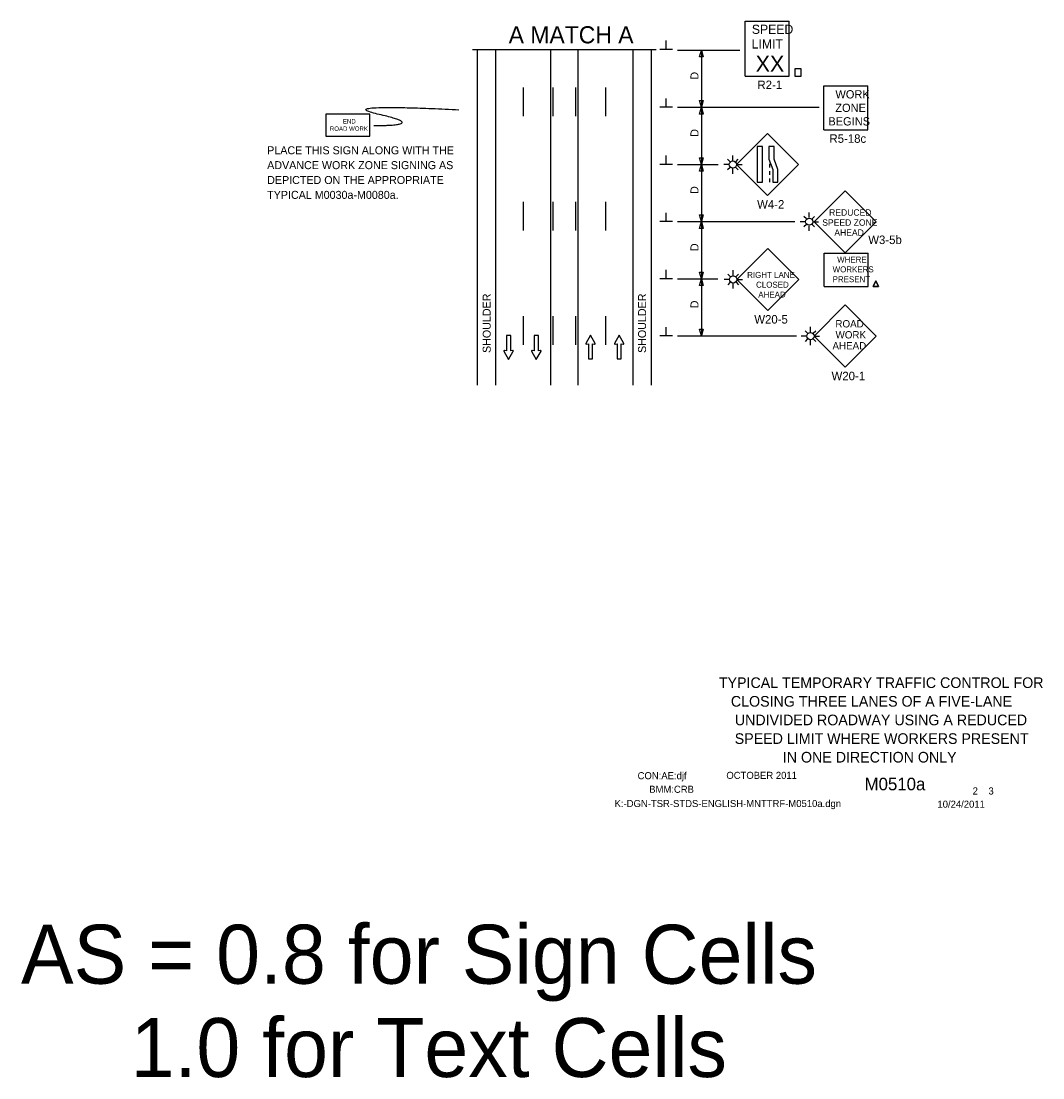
# Model space of a CAD drawing. Extents: x 16730 to 19504, y 5697 to 6911.
# Drawn here: x 17580 to 18474, y 5697 to 6621 of the extents above; entities that cross this region are included whole.
import ezdxf

# ---------------------------------------------------------------- set-up
doc = ezdxf.new("R2010")
doc.units = 0
for name, color, linetype in [('ALI_LEGAL_EX', 7, 'Continuous'), ('BORDER', 7, 'Continuous'), ('BORDER_SIGNAL_WO', 7, 'Continuous'), ('MT_SCRATCH_LEVEL_E', 7, 'Continuous'), ('PAVT_EDGE_EX', 7, 'Continuous'), ('TRAFFIC_SIGNS_PR', 7, 'Continuous'), ('TYPICAL_TEXT_DIMEN_PR', 7, 'Continuous')]:
    doc.layers.add(name, color=color, linetype=linetype)

msp = doc.modelspace()

# ---------------------------------------------------------------- linework, layer by layer
at = {"layer": 'ALI_LEGAL_EX'}
for points in [[(18019.48, 6563.08), (18019.48, 6538.08)], [(18045.48, 6563.08), (18045.48, 6538.08)], [(18065.48, 6563.08), (18065.48, 6538.08)], [(18091.48, 6563.08), (18091.48, 6538.08)], [(18019.48, 6463.08), (18019.48, 6438.08)], [(18045.48, 6463.08), (18045.48, 6438.08)], [(18065.48, 6463.08), (18065.48, 6438.08)], [(18091.48, 6463.08), (18091.48, 6438.08)], [(18019.48, 6363.08), (18019.48, 6338.08)], [(18045.48, 6363.08), (18045.48, 6338.08)], [(18065.48, 6363.08), (18065.48, 6338.08)], [(18091.48, 6363.08), (18091.48, 6338.08)]]:
    msp.add_lwpolyline(points, dxfattribs=at)
at = {"layer": 'MT_SCRATCH_LEVEL_E'}
for p, q in [((18008.68, 6346.05), (18004.93, 6346.05)), ((18004.93, 6346.05), (18004.93, 6332.79)), ((18008.68, 6346.05), (18004.93, 6346.05)), ((18004.93, 6346.05), (18004.93, 6332.79)), ((18008.68, 6332.79), (18008.68, 6346.05)), ((18008.68, 6332.79), (18008.68, 6346.05)), ((18032.93, 6346.05), (18029.19, 6346.05)), ((18029.19, 6346.05), (18029.19, 6332.79)), ((18032.93, 6346.05), (18029.19, 6346.05)), ((18029.19, 6346.05), (18029.19, 6332.79)), ((18032.93, 6332.79), (18032.93, 6346.05)), ((18032.93, 6332.79), (18032.93, 6346.05)), ((18078.44, 6346.51), (18074.33, 6339.27)), ((18078.44, 6346.51), (18074.33, 6339.27)), ((18082.59, 6339.27), (18078.44, 6346.51)), ((18082.59, 6339.27), (18078.44, 6346.51)), ((18103.53, 6346.51), (18099.42, 6339.27)), ((18103.53, 6346.51), (18099.42, 6339.27)), ((18107.68, 6339.27), (18103.53, 6346.51)), ((18107.68, 6339.27), (18103.53, 6346.51)), ((18002.68, 6332.42), (18006.82, 6325.18)), ((18002.68, 6332.42), (18006.82, 6325.18)), ((18004.93, 6332.79), (18003.16, 6333.11)), ((18004.93, 6332.79), (18003.16, 6333.11)), ((18006.82, 6325.18), (18010.94, 6332.42)), ((18006.82, 6325.18), (18010.94, 6332.42)), ((18010.45, 6333.11), (18008.68, 6332.79)), ((18010.45, 6333.11), (18008.68, 6332.79)), ((18026.93, 6332.42), (18031.08, 6325.18)), ((18026.93, 6332.42), (18031.08, 6325.18)), ((18029.19, 6332.79), (18027.41, 6333.11)), ((18029.19, 6332.79), (18027.41, 6333.11)), ((18031.08, 6325.18), (18035.19, 6332.42)), ((18031.08, 6325.18), (18035.19, 6332.42)), ((18034.71, 6333.11), (18032.93, 6332.79)), ((18034.71, 6333.11), (18032.93, 6332.79)), ((18074.81, 6338.59), (18076.59, 6338.9)), ((18074.81, 6338.59), (18076.59, 6338.9)), ((18076.59, 6338.9), (18076.59, 6325.64)), ((18076.59, 6338.9), (18076.59, 6325.64)), ((18080.33, 6325.64), (18080.33, 6338.9)), ((18080.33, 6338.9), (18082.11, 6338.59)), ((18080.33, 6325.64), (18080.33, 6338.9)), ((18080.33, 6338.9), (18082.11, 6338.59)), ((18099.9, 6338.59), (18101.68, 6338.9)), ((18099.9, 6338.59), (18101.68, 6338.9)), ((18101.68, 6338.9), (18101.68, 6325.64)), ((18101.68, 6338.9), (18101.68, 6325.64)), ((18105.42, 6325.64), (18105.42, 6338.9)), ((18105.42, 6338.9), (18107.2, 6338.59)), ((18105.42, 6325.64), (18105.42, 6338.9)), ((18105.42, 6338.9), (18107.2, 6338.59)), ((18076.59, 6325.64), (18080.33, 6325.64)), ((18076.59, 6325.64), (18080.33, 6325.64)), ((18101.68, 6325.64), (18105.42, 6325.64)), ((18101.68, 6325.64), (18105.42, 6325.64))]:
    msp.add_line(p, q, dxfattribs=at)
for centre, start, end in [((18003.09, 6332.65), 80.03619, 209.77312), ((18003.09, 6332.65), 80.03619, 209.77312), ((18010.53, 6332.65), 330.42484, 99.96381), ((18010.53, 6332.65), 330.42484, 99.96381), ((18027.34, 6332.65), 80.03619, 209.77312), ((18027.34, 6332.65), 80.03619, 209.77312), ((18034.78, 6332.65), 330.42484, 99.96381), ((18034.78, 6332.65), 330.42484, 99.96381), ((18074.74, 6339.05), 150.42484, 279.96381), ((18074.74, 6339.05), 150.42484, 279.96381), ((18082.18, 6339.05), 260.03619, 29.77312), ((18082.18, 6339.05), 260.03619, 29.77312), ((18099.83, 6339.05), 150.42484, 279.96381), ((18099.83, 6339.05), 150.42484, 279.96381), ((18107.27, 6339.05), 260.03619, 29.77312), ((18107.27, 6339.05), 260.03619, 29.77312)]:
    msp.add_arc(centre, 0.463, start, end, dxfattribs=at)
at = {"layer": 'PAVT_EDGE_EX'}
for p, q in [((17979.48, 6596.43), (17979.48, 6302.77)), ((17995.48, 6596.43), (17995.48, 6302.77)), ((18043.48, 6596.43), (18043.48, 6302.77)), ((18067.48, 6596.43), (18067.48, 6302.77)), ((18115.48, 6596.43), (18115.48, 6302.77)), ((18131.48, 6596.43), (18131.48, 6302.77))]:
    msp.add_line(p, q, dxfattribs=at)
at = {"layer": 'TRAFFIC_SIGNS_PR'}
for p, q in [((18213.83, 6621.17), (18252.23, 6621.17)), ((18213.83, 6573.17), (18213.83, 6621.17)), ((18252.23, 6573.17), (18252.23, 6621.17)), ((18213.83, 6573.17), (18252.23, 6573.17)), ((18282.71, 6526.17), (18282.71, 6564.57)), ((18282.71, 6564.57), (18321.11, 6564.57)), ((18321.11, 6526.17), (18321.11, 6564.57)), ((18282.71, 6526.17), (18321.11, 6526.17)), ((18233.28, 6522.93), (18206.12, 6495.78)), ((18260.43, 6495.78), (18233.28, 6522.93)), ((18200.52, 6498.23), (18198.42, 6500.34)), ((18203.04, 6499.28), (18203.04, 6503.78)), ((18205.55, 6498.23), (18207.66, 6500.34)), ((18199.88, 6495.72), (18195.05, 6495.72)), ((18200.52, 6493.21), (18198.42, 6491.1)), ((18203.04, 6487.75), (18203.04, 6492.17)), ((18205.55, 6493.21), (18207.66, 6491.1)), ((18206.12, 6495.78), (18233.28, 6468.63)), ((18206.19, 6495.72), (18211.07, 6495.72)), ((18233.28, 6468.63), (18260.43, 6495.78)), ((18234.92, 6496.27), (18234.92, 6493.07)), ((18234.92, 6489.87), (18234.92, 6486.67)), ((18234.92, 6483.47), (18234.92, 6480.27)), ((18301.14, 6472.83), (18273.99, 6445.68)), ((18328.3, 6445.68), (18301.14, 6472.83)), ((18269.79, 6449.31), (18269.79, 6453.81)), ((18266.64, 6445.76), (18261.8, 6445.76)), ((18267.28, 6448.27), (18265.17, 6450.38)), ((18267.28, 6443.24), (18265.17, 6441.13)), ((18272.3, 6448.27), (18274.41, 6450.38)), ((18272.3, 6443.24), (18274.41, 6441.14)), ((18272.94, 6445.76), (18277.82, 6445.76)), ((18273.99, 6445.68), (18301.14, 6418.53)), ((18301.14, 6418.53), (18328.3, 6445.68)), ((18269.79, 6437.79), (18269.79, 6442.2)), ((18233.57, 6422.38), (18206.42, 6395.23)), ((18260.72, 6395.23), (18233.57, 6422.38)), ((18282.88, 6418.35), (18321.28, 6418.35)), ((18282.88, 6389.03), (18282.88, 6418.35)), ((18321.28, 6389.03), (18321.28, 6418.35)), ((18200.75, 6397.74), (18198.64, 6399.85)), ((18203.26, 6398.78), (18203.26, 6403.28)), ((18205.78, 6397.74), (18207.89, 6399.85)), ((18200.11, 6395.23), (18195.27, 6395.23)), ((18200.75, 6392.71), (18198.64, 6390.6)), ((18203.26, 6387.26), (18203.26, 6391.67)), ((18205.78, 6392.71), (18207.88, 6390.61)), ((18206.42, 6395.23), (18211.3, 6395.23)), ((18206.42, 6395.23), (18233.57, 6368.07)), ((18233.57, 6368.07), (18260.72, 6395.23)), ((18282.88, 6389.03), (18321.28, 6389.03)), ((18301.17, 6372.88), (18273.99, 6345.69)), ((18328.36, 6345.69), (18301.17, 6372.88)), ((18268.32, 6348.2), (18266.21, 6350.31)), ((18270.83, 6349.25), (18270.83, 6353.75)), ((18273.35, 6348.2), (18275.46, 6350.31)), ((18267.68, 6345.69), (18262.84, 6345.69)), ((18268.32, 6343.18), (18266.21, 6341.07)), ((18270.83, 6337.72), (18270.83, 6342.14)), ((18273.35, 6343.18), (18275.45, 6341.07)), ((18273.99, 6345.69), (18278.87, 6345.69)), ((18273.99, 6345.69), (18301.17, 6318.5)), ((18301.17, 6318.5), (18328.36, 6345.69))]:
    msp.add_line(p, q, dxfattribs=at)
for points in [[(18257.25, 6573.17), (18262.84, 6573.17), (18262.84, 6579.34), (18257.25, 6579.34)], [(17846.94, 6520.48), (17885.34, 6520.48), (17885.34, 6539.68), (17846.94, 6539.68)], [(18224.38, 6511.52), (18224.38, 6480.27), (18228.87, 6480.27), (18228.87, 6511.52)], [(18234.52, 6511.52), (18234.52, 6500.33), (18237.86, 6491.45), (18237.86, 6480.27), (18242.35, 6480.27), (18242.35, 6491.45), (18239.01, 6500.33), (18239.01, 6511.52)]]:
    msp.add_lwpolyline(points, close=True, dxfattribs=at)
for points in [[(18328.03, 6393.97), (18325.8, 6389.03)], [(18325.8, 6389.03), (18328.03, 6393.97)], [(18325.8, 6389.03), (18330.27, 6389.03)], [(18330.27, 6389.03), (18325.8, 6389.03)], [(18330.27, 6389.03), (18328.03, 6393.97)], [(18328.03, 6393.97), (18330.27, 6389.03)]]:
    msp.add_lwpolyline(points, dxfattribs=at)
for centre in [(18203.04, 6495.72), (18269.79, 6445.76), (18203.26, 6395.23), (18270.83, 6345.69)]:
    msp.add_circle(centre, 3.15, dxfattribs=at)
msp.add_open_spline([(17888.94, 6529.86), (17936.17, 6529.86), (17851.15, 6549.2), (17963.45, 6543.71)], degree=2, dxfattribs=at)
at = {"layer": 'TYPICAL_TEXT_DIMEN_PR'}
for p, q in [((18144.61, 6596.43), (18144.61, 6604.22)), ((17975.18, 6596.43), (18135.78, 6596.43)), ((18150.23, 6596.43), (18138.98, 6596.43)), ((18154.48, 6595.78), (18209.14, 6595.78)), ((18173.91, 6589.92), (18175.48, 6595.78)), ((18175.48, 6595.78), (18175.48, 6545.78)), ((18175.48, 6595.78), (18177.05, 6589.92)), ((18175.48, 6589.92), (18173.91, 6589.92)), ((18177.05, 6589.92), (18175.48, 6589.92)), ((18144.61, 6545.78), (18144.61, 6553.57)), ((18150.23, 6545.78), (18138.98, 6545.78)), ((18154.48, 6545.78), (18278.43, 6545.78)), ((18175.48, 6545.78), (18173.91, 6551.65)), ((18173.91, 6551.65), (18175.48, 6551.65)), ((18173.91, 6539.92), (18175.48, 6545.78)), ((18175.48, 6551.65), (18177.05, 6551.65)), ((18177.05, 6551.65), (18175.48, 6545.78)), ((18175.48, 6545.78), (18175.48, 6495.78)), ((18175.48, 6545.78), (18177.05, 6539.92)), ((18175.48, 6539.92), (18173.91, 6539.92)), ((18177.05, 6539.92), (18175.48, 6539.92)), ((18144.61, 6495.78), (18144.61, 6503.57)), ((18175.48, 6495.78), (18173.91, 6501.65)), ((18173.91, 6501.65), (18175.48, 6501.65)), ((18175.48, 6495.78), (18173.91, 6501.65)), ((18173.91, 6501.65), (18175.48, 6501.65)), ((18175.48, 6501.65), (18177.05, 6501.65)), ((18177.05, 6501.65), (18175.48, 6495.78)), ((18175.48, 6501.65), (18177.05, 6501.65)), ((18177.05, 6501.65), (18175.48, 6495.78)), ((18150.23, 6495.78), (18138.98, 6495.78)), ((18154.48, 6495.78), (18190.26, 6495.78)), ((18173.91, 6489.92), (18175.48, 6495.78)), ((18175.48, 6489.92), (18173.91, 6489.92)), ((18175.48, 6495.78), (18175.48, 6445.78)), ((18175.48, 6495.78), (18177.05, 6489.92)), ((18177.05, 6489.92), (18175.48, 6489.92)), ((18144.61, 6445.78), (18144.61, 6453.57)), ((18150.23, 6445.78), (18138.98, 6445.78)), ((18154.48, 6445.78), (18257.28, 6445.78)), ((18175.48, 6445.78), (18173.91, 6451.65)), ((18173.91, 6451.65), (18175.48, 6451.65)), ((18173.91, 6439.92), (18175.48, 6445.78)), ((18175.48, 6451.65), (18177.05, 6451.65)), ((18177.05, 6451.65), (18175.48, 6445.78)), ((18175.48, 6445.78), (18175.48, 6395.78)), ((18175.48, 6445.78), (18177.05, 6439.92)), ((18175.48, 6439.92), (18173.91, 6439.92)), ((18177.05, 6439.92), (18175.48, 6439.92)), ((18144.61, 6395.78), (18144.61, 6403.57)), ((18175.48, 6395.78), (18173.91, 6401.65)), ((18173.91, 6401.65), (18175.48, 6401.65)), ((18175.48, 6401.65), (18177.05, 6401.65)), ((18177.05, 6401.65), (18175.48, 6395.78)), ((18150.23, 6395.78), (18138.98, 6395.78)), ((18154.48, 6395.78), (18189.76, 6395.78)), ((18173.91, 6389.92), (18175.48, 6395.78)), ((18175.48, 6389.92), (18173.91, 6389.92)), ((18175.48, 6395.78), (18175.48, 6345.78)), ((18175.48, 6395.78), (18177.05, 6389.92)), ((18177.05, 6389.92), (18175.48, 6389.92)), ((18144.61, 6345.78), (18144.61, 6353.57)), ((18175.48, 6345.78), (18173.91, 6351.65)), ((18173.91, 6351.65), (18175.48, 6351.65)), ((18175.48, 6351.65), (18177.05, 6351.65)), ((18177.05, 6351.65), (18175.48, 6345.78)), ((18150.23, 6345.78), (18138.98, 6345.78)), ((18154.48, 6345.78), (18258.56, 6345.78))]:
    msp.add_line(p, q, dxfattribs=at)

# ---------------------------------------------------------------- texts
at = {"layer": 'BORDER'}
for s, p in [('TYPICAL TEMPORARY TRAFFIC CONTROL FOR', (18190.75, 6037.86)), ('CLOSING THREE LANES OF A FIVE-LANE', (18201.26, 6021.56)), ('UNDIVIDED ROADWAY USING A REDUCED', (18204.72, 6005.26)), ('SPEED LIMIT WHERE WORKERS PRESENT', (18204.62, 5988.96)), ('IN ONE DIRECTION ONLY', (18246.69, 5972.66))]:
    msp.add_text(s, height=9.3, dxfattribs=at).set_placement(p)
at = {"layer": 'BORDER_SIGNAL_WO'}
for s, height, p in [('CON:AE:djf', 6.2, (18119.69, 5958.06)), ('    OCTOBER 2011    ', 6.2, (18188.08, 5958.34)), ('    M0510a   ', 11, (18301.86, 5948.38)), ('BMM:CRB   ', 6.2, (18129.81, 5946.17)), (' 2    3 ', 6.2, (18410.45, 5944.7)), ('K:-DGN-TSR-STDS-ENGLISH-MNTTRF-M0510a.dgn        ', 6.2, (18099.55, 5933.71)), ('10/24/2011    ', 6.2, (18381.93, 5933.13)), ('AS = 0.8 for Sign Cells', 51.6096, (17580.32, 5779.18)), ('     1.0 for Text Cells', 51.6096, (17580.32, 5697.57))]:
    msp.add_text(s, height=height, dxfattribs=at).set_placement(p)
at = {"layer": 'TRAFFIC_SIGNS_PR'}
for s, height, p in [('SPEED', 8, (18219.6, 6610.03)), ('LIMIT', 8, (18219.44, 6597.23)), ('XX', 14.031, (18222.94, 6576.93)), ('R2-1', 7.44, (18224.51, 6561.73)), ('WORK', 7.217, (18292.71, 6553.54)), ('ZONE', 7.217, (18292.59, 6541.73)), ('END', 3.831, (17861.95, 6531.61)), ('BEGINS', 7.217, (18286.52, 6529.92)), ('ROAD WORK', 3.831, (17850.55, 6525.22)), ('R5-18c', 7.44, (18287.52, 6514.73)), ('PLACE THIS SIGN ALONG WITH THE', 7, (17795.67, 6504.7)), ('ADVANCE WORK ZONE SIGNING AS', 7, (17795.67, 6491.7)), ('DEPICTED ON THE APPROPRIATE', 7, (17795.67, 6478.7)), ('TYPICAL M0030a-M0080a.', 7, (17795.67, 6465.7)), ('W4-2', 7.44, (18224.23, 6457.19)), ('REDUCED', 5.6, (18287.2, 6450.99)), ('SPEED ZONE', 5.6, (18281.19, 6442.19)), ('AHEAD', 5.6, (18291.75, 6433.39)), ('W3-5b', 7.44, (18321.43, 6426.18)), ('WHERE', 5.2, (18294.2, 6410.03)), ('WORKERS', 5.2, (18290.27, 6401.43)), ('RIGHT LANE', 5.2, (18215.49, 6396.62)), ('PRESENT', 5.2, (18290.2, 6392.83)), ('CLOSED', 5.2, (18223.28, 6388.02)), ('AHEAD', 5.2, (18225.23, 6379.42)), ('W20-5', 7.44, (18221.74, 6356.63)), ('ROAD', 6.408, (18292.7, 6353.24)), ('WORK', 6.408, (18292.81, 6343.62)), ('AHEAD', 6.408, (18290.12, 6334.01)), ('W20-1', 7.449, (18289.33, 6307.05))]:
    msp.add_text(s, height=height, dxfattribs=at).set_placement(p)
at = {"layer": 'TYPICAL_TEXT_DIMEN_PR'}
msp.add_text('A MATCH A', height=15, dxfattribs=at).set_placement((18006.9, 6601.72))
for s, p in [('D', (18172.92, 6570)), ('D', (18172.92, 6520)), ('D', (18172.92, 6470)), ('D', (18172.92, 6420)), ('SHOULDER', (17991.17, 6330.9)), ('SHOULDER', (18127.07, 6330.9)), ('D', (18172.92, 6370))]:
    msp.add_text(s, height=7, rotation=90, dxfattribs=at).set_placement(p)

doc.saveas('drawing.dxf')
